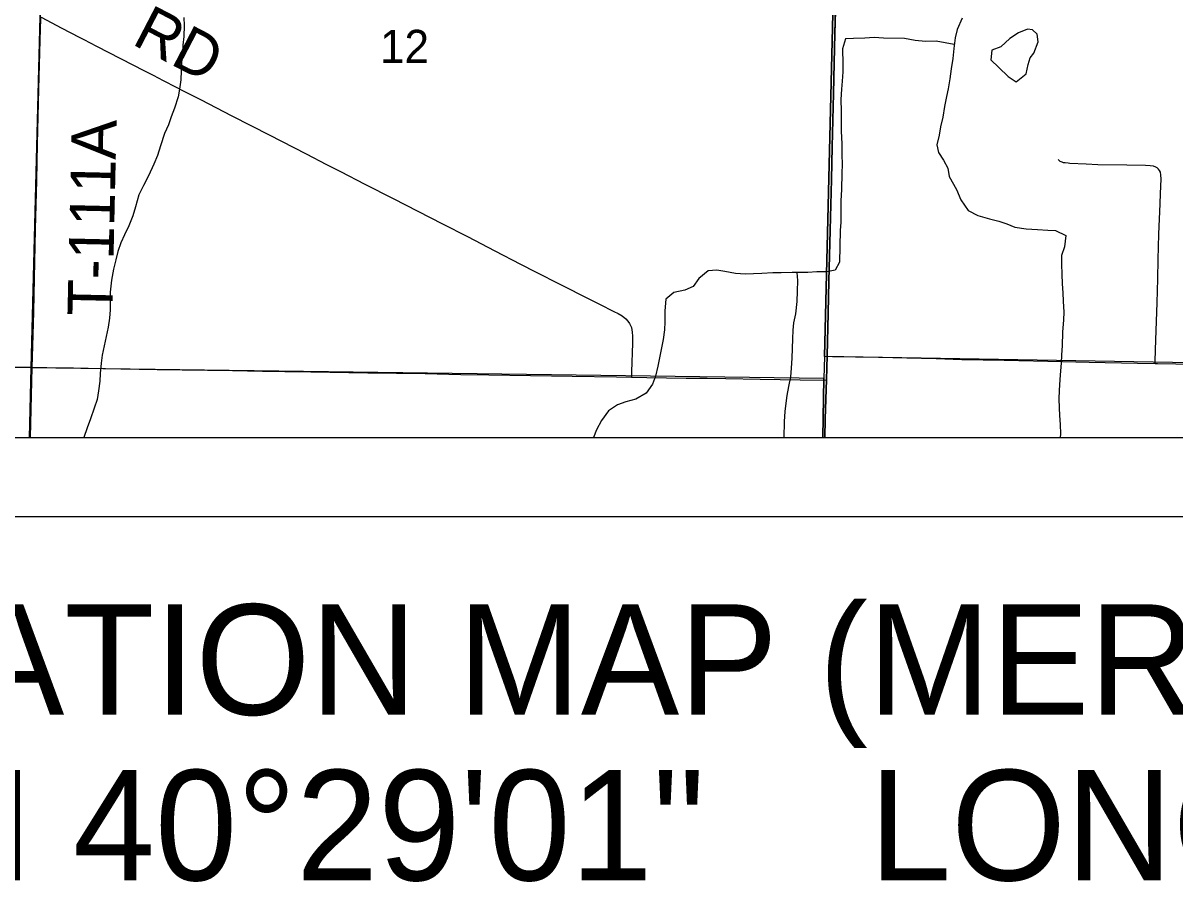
# Model space of a CAD drawing. Extents: x -38.1 to 35.9, y -2.7 to 28.5.
# Drawn here: x 20.873 to 22.334, y 12.367 to 13.456 of the extents above; entities that cross this region are included whole.
import ezdxf

# ---------------------------------------------------------------- set-up
doc = ezdxf.new("R2010")
doc.units = 0
for name, color, linetype in [('GM_X_City_Street_Text', 7, 'Continuous'), ('GM_X_Interchange_Ramps', 7, 'Continuous'), ('GM_X_Major_River', 7, 'Continuous'), ('GM_X_Major_River_Text', 7, 'Continuous'), ('GM_X_Minor_Lake', 7, 'Continuous'), ('GM_X_Minor_River', 7, 'Continuous'), ('GM_X_Section', 7, 'Continuous'), ('GM_X_Township', 7, 'Continuous'), ('GM_X_US_Route', 7, 'Continuous'), ('SC_Scratch10', 7, 'Continuous'), ('SH_Border', 7, 'Continuous'), ('SH_Data', 7, 'Continuous')]:
    doc.layers.add(name, color=color, linetype=linetype)

msp = doc.modelspace()

# ---------------------------------------------------------------- linework, layer by layer
at = {"layer": 'GM_X_City_Street_Text'}
for points in [[(20.8958, 13.464), (20.9221, 13.4499), (20.9442, 13.4385), (20.9503, 13.4353), (20.9663, 13.4271), (21.0271, 13.3959), (21.0382, 13.3902), (21.0508, 13.3836), (21.0674, 13.3751), (21.0762, 13.3705), (21.0989, 13.3589), (21.137, 13.3393), (21.163, 13.3259), (21.1851, 13.3145), (21.2321, 13.2904), (21.2581, 13.2771), (21.2758, 13.2681), (21.3067, 13.2521), (21.3427, 13.2338), (21.4052, 13.2019), (21.4368, 13.1857), (21.4715, 13.1677), (21.504, 13.1508), (21.5101, 13.1477), (21.5173, 13.144), (21.5605, 13.122), (21.5848, 13.1096), (21.6043, 13.0998), (21.6226, 13.0907), (21.6277, 13.0881), (21.6331, 13.0849), (21.6376, 13.0813), (21.6401, 13.0785), (21.6424, 13.0753), (21.6447, 13.0701), (21.6458, 13.0644), (21.6462, 13.0594), (21.6462, 13.0506), (21.6447, 13.014), (21.6448, 13.0074)], [(19.8814, 13.0339), (19.8972, 13.0337), (19.9594, 13.0327), (19.9936, 13.0323), (20.0346, 13.0318), (20.0718, 13.0311), (20.1185, 13.0304), (20.1613, 13.0299), (20.2421, 13.0289), (20.2744, 13.0285), (20.3322, 13.0277), (20.3894, 13.0267), (20.4366, 13.0263), (20.4913, 13.0255), (20.5205, 13.0251), (20.5938, 13.024), (20.6255, 13.0234), (20.6939, 13.0224), (20.7293, 13.0219), (20.7777, 13.0212), (20.8337, 13.0203), (20.8845, 13.0198)], [(20.8845, 13.0198), (20.9032, 13.0194), (20.9368, 13.019), (20.9741, 13.0182), (21.0431, 13.0171), (21.1387, 13.0157), (21.1766, 13.015), (21.2052, 13.0145), (21.2382, 13.0142), (21.3102, 13.013), (21.383, 13.0119), (21.4283, 13.0109), (21.4637, 13.0104), (21.5694, 13.0088), (21.6259, 13.0079), (21.6448, 13.0074)], [(21.6448, 13.0074), (21.6644, 13.007), (21.7141, 13.006), (21.7408, 13.0059), (21.7644, 13.0057), (21.8079, 13.005), (21.8589, 13.004), (21.8922, 13.0036)]]:
    msp.add_lwpolyline(points, dxfattribs=at)
at = {"layer": 'GM_X_Interchange_Ramps'}
msp.add_lwpolyline([(21.893, 13.0338), (21.8997, 13.0337), (21.9581, 13.0327), (21.9941, 13.0317), (22.0314, 13.0308), (22.0637, 13.0299), (22.1177, 13.0288), (22.1917, 13.0273), (22.2252, 13.0264), (22.2867, 13.0251), (22.3091, 13.0247), (22.3122, 13.0246), (22.3352, 13.0244), (22.3581, 13.024), (22.3768, 13.0237), (22.4268, 13.0227), (22.437, 13.0226)], dxfattribs=at)
at = {"layer": 'GM_X_Major_River'}
msp.add_lwpolyline([(21.8903, 12.9308), (21.8908, 12.9539), (21.8922, 13.0036), (21.893, 13.0338), (21.8944, 13.088), (21.8955, 13.129), (21.8972, 13.1932), (21.8987, 13.2576), (21.8996, 13.2986), (21.9011, 13.3663), (21.902, 13.4048), (21.9031, 13.4427), (21.9038, 13.4717)], dxfattribs=at)
at = {"layer": 'GM_X_Major_River_Text'}
msp.add_line((20.8823, 12.9308), (20.8845, 13.0198), dxfattribs=at)
for points in [[(20.8845, 13.0198), (20.8854, 13.0465), (20.8866, 13.09), (20.8881, 13.1534), (20.889, 13.195), (20.8903, 13.2565), (20.8914, 13.3031), (20.8931, 13.3727), (20.8949, 13.4348), (20.8957, 13.4621), (20.8958, 13.464)], [(22.3091, 13.0247), (22.3092, 13.0279), (22.3101, 13.0546), (22.3116, 13.1017), (22.3125, 13.1321), (22.313, 13.1565), (22.3136, 13.1888), (22.3153, 13.2273), (22.3158, 13.2403), (22.3166, 13.2583), (22.3164, 13.2638), (22.3157, 13.2673), (22.3146, 13.2696), (22.3134, 13.2712), (22.3118, 13.2727), (22.3098, 13.2738), (22.307, 13.2748), (22.3029, 13.2755), (22.2967, 13.2757), (22.2731, 13.2761), (22.2365, 13.2767), (22.2215, 13.2773), (22.2007, 13.2783), (22.1987, 13.2785), (22.1948, 13.2789), (22.1926, 13.2793), (22.191, 13.2798), (22.1897, 13.2803), (22.1886, 13.281), (22.1859, 13.2833)]]:
    msp.add_lwpolyline(points, dxfattribs=at)
at = {"layer": 'GM_X_Section'}
for points in [[(21.077, 13.4636), (21.0775, 13.4533), (21.0768, 13.4392), (21.0758, 13.4282), (21.0752, 13.418), (21.0738, 13.4062), (21.0736, 13.3959), (21.073, 13.3842), (21.0716, 13.3724), (21.0699, 13.3626), (21.065, 13.3486), (21.0609, 13.3373), (21.0573, 13.3275), (21.0525, 13.3165), (21.0472, 13.3007), (21.0436, 13.2882), (21.0391, 13.2773), (21.032, 13.2626), (21.0256, 13.2502), (21.0197, 13.2385), (21.0156, 13.2234), (21.0123, 13.2117), (21.0071, 13.1993), (21.0019, 13.188), (20.9971, 13.1778), (20.9934, 13.1665), (20.9906, 13.1559), (20.9876, 13.1442), (20.9851, 13.1305), (20.9836, 13.115), (20.9834, 13.1039), (20.9835, 13.0925), (20.9825, 13.0823), (20.9811, 13.0709), (20.9786, 13.0591), (20.9757, 13.047), (20.9735, 13.0353), (20.9722, 13.025), (20.9707, 13.0118), (20.9702, 13.0023), (20.9688, 12.9901), (20.967, 12.9791), (20.9633, 12.9682), (20.9585, 12.9546), (20.9544, 12.9429), (20.9499, 12.9308)], [(22.0644, 13.4624), (22.058, 13.4481), (22.0555, 13.4375), (22.0536, 13.4242), (22.0526, 13.4113), (22.0504, 13.3981), (22.0486, 13.3856), (22.0465, 13.3731), (22.0443, 13.3632), (22.0418, 13.3507), (22.0396, 13.3371), (22.0367, 13.3246), (22.0349, 13.314), (22.032, 13.3019), (22.0341, 13.2923), (22.0407, 13.2827), (22.0462, 13.2723), (22.0478, 13.2616), (22.057, 13.2454), (22.0624, 13.232), (22.072, 13.2188), (22.084, 13.2125), (22.0991, 13.208), (22.1108, 13.205), (22.121, 13.2018), (22.1312, 13.1977), (22.1456, 13.1955), (22.1596, 13.1944), (22.1729, 13.1937), (22.1827, 13.1931), (22.1959, 13.1871), (22.1941, 13.1727), (22.1904, 13.1618), (22.1902, 13.1508), (22.1907, 13.1378), (22.1912, 13.1256), (22.192, 13.1142), (22.1922, 13.1039), (22.193, 13.0899), (22.1928, 13.08), (22.1917, 13.0644), (22.191, 13.0469), (22.1903, 13.0355), (22.1897, 13.0249), (22.1891, 13.0154), (22.1881, 13.0044), (22.1871, 12.9903), (22.1868, 12.9797), (22.1874, 12.9683), (22.1875, 12.9588), (22.1884, 12.9473), (22.1889, 12.9355), (22.1885, 12.9308)], [(22.0543, 13.4293), (22.0314, 13.4335), (22.0177, 13.433), (22.0045, 13.4341), (21.9912, 13.4367), (21.9643, 13.4373), (21.9525, 13.4379), (21.9407, 13.4374), (21.9263, 13.4366), (21.9164, 13.4365), (21.9123, 13.4236), (21.9127, 13.4046), (21.9128, 13.3943), (21.9122, 13.3826), (21.9112, 13.3727), (21.9105, 13.3594), (21.9106, 13.3446), (21.9107, 13.3305), (21.9108, 13.3191), (21.9116, 13.3031), (21.9117, 13.2898), (21.9122, 13.2772), (21.9115, 13.2658), (21.9111, 13.2453), (21.9104, 13.2309), (21.9104, 13.2153), (21.9102, 13.2039), (21.9096, 13.1932), (21.9087, 13.1533), (21.9032, 13.1428), (21.8925, 13.1411), (21.88, 13.1407), (21.8685, 13.1402), (21.8587, 13.14), (21.8488, 13.1402), (21.8347, 13.1398), (21.8241, 13.1396), (21.81, 13.1388), (21.7994, 13.1383), (21.7895, 13.1378), (21.7766, 13.1388), (21.7633, 13.1414), (21.7531, 13.1428), (21.7421, 13.1423), (21.7301, 13.1326), (21.723, 13.1225), (21.7123, 13.1178), (21.6986, 13.1147), (21.6885, 13.1062), (21.687, 13.0914), (21.6871, 13.0777), (21.6865, 13.0674), (21.6851, 13.0553), (21.6826, 13.0424), (21.6804, 13.0318), (21.6783, 13.0212), (21.6754, 13.0087), (21.6714, 12.9986), (21.6635, 12.9869), (21.6504, 12.9796), (21.6378, 12.9761), (21.6271, 12.9722), (21.6155, 12.9648), (21.6069, 12.9525), (21.6006, 12.9404), (21.5968, 12.9308)], [(21.8545, 13.1401), (21.8554, 13.1298), (21.8551, 13.1165), (21.8545, 13.1032), (21.853, 13.0876), (21.8501, 13.0763), (21.8495, 13.0668), (21.8489, 13.0558), (21.8483, 13.0315), (21.8473, 13.0189), (21.8463, 13.0079), (21.8441, 12.9954), (21.842, 12.9841), (21.8406, 12.9742), (21.8393, 12.9636), (21.8386, 12.951), (21.8382, 12.9308)]]:
    msp.add_lwpolyline(points, dxfattribs=at)
at = {"layer": 'GM_X_US_Route'}
for points in [[(19.9045, 14.0411), (20.909, 14.026), (20.8833, 13.0192), (19.8751, 13.0369)], [(21.9144, 14.0375), (23.0161, 14.0176), (22.9932, 13.0145), (21.8896, 13.0337), (21.9134, 14.0076)], [(20.909, 14.026), (21.9134, 14.0076), (21.8896, 13.0337), (21.8889, 13.0056), (20.8833, 13.0192)], [(18.6101, 13.5671), (18.6101, 12.9308), (21.8901, 12.9308), (21.8906, 12.9544), (21.892, 13.0041), (21.8928, 13.0344), (21.8942, 13.0886), (21.8952, 13.1296), (21.8969, 13.1937), (21.8985, 13.2581), (21.8993, 13.2992), (21.9009, 13.3669), (21.9018, 13.4054), (21.9029, 13.4433), (21.9044, 13.5072), (20.8967, 13.5231), (20.7889, 13.5255), (19.8942, 13.5382), (18.8863, 13.5601)], [(19.8726, 12.9308), (20.8814, 12.9308), (20.8833, 13.0192), (19.8751, 13.0369)], [(20.8814, 12.9308), (21.8874, 12.9308), (21.8889, 13.0056), (20.8833, 13.0192)], [(21.8874, 12.9308), (22.991, 12.9308), (22.9932, 13.0145), (21.8896, 13.0337), (21.8889, 13.0056)]]:
    msp.add_lwpolyline(points, close=True, dxfattribs=at)
msp.add_lwpolyline([(21.9044, 13.5072), (21.9029, 13.4433), (21.9018, 13.4054), (21.9009, 13.3669), (21.8993, 13.2992), (21.8985, 13.2581), (21.8969, 13.1937), (21.8952, 13.1296), (21.8942, 13.0886), (21.8928, 13.0344), (21.892, 13.0041), (21.8906, 12.9544), (21.8901, 12.9308), (25.4101, 12.9308)], dxfattribs=at)
at = {"layer": 'SC_Scratch10'}
for points in [[(22.1478, 13.4037), (22.1503, 13.4122), (22.1553, 13.4181), (22.1606, 13.4325), (22.1593, 13.4424), (22.1533, 13.4478), (22.1473, 13.4487), (22.1358, 13.444), (22.1246, 13.4367)], [(22.1246, 13.4367), (22.1133, 13.4263), (22.1018, 13.422), (22.1004, 13.4099), (22.1109, 13.4001), (22.1224, 13.3885), (22.1329, 13.3818), (22.1453, 13.3921), (22.1478, 13.4037)]]:
    msp.add_lwpolyline(points, dxfattribs=at)
at = {"layer": 'SH_Border'}
msp.add_line((18.6101, 12.9308), (25.4101, 12.9308), dxfattribs=at)
at = {"layer": 'SH_Data'}
msp.add_line((18.5101, 12.8308), (25.5101, 12.8308), dxfattribs=at)

# ---------------------------------------------------------------- texts
at = {"layer": 'GM_X_Minor_Lake'}
msp.add_text('T-111A', height=0.05682, rotation=88.7089, dxfattribs=at).set_placement((20.9861, 13.0844))
at = {"layer": 'GM_X_Minor_River'}
msp.add_text('12', height=0.04186, rotation=0, dxfattribs=at).set_placement((21.3257, 13.4059))
at = {"layer": 'GM_X_Township'}
msp.add_text('RD', height=0.05682, rotation=332.5568, dxfattribs=at).set_placement((21.0095, 13.4303))
at = {"layer": 'SH_Data'}
for s, p in [('LOCATION MAP (MER-US127-8.981)', (20.4156, 12.5792)), ('LATITUDE: N 40°29\'01"    LONGITUDE: W 84°34\'17" ', (19.7401, 12.3692))]:
    msp.add_text(s, height=0.14, dxfattribs=at).set_placement(p)

doc.saveas('drawing.dxf')
